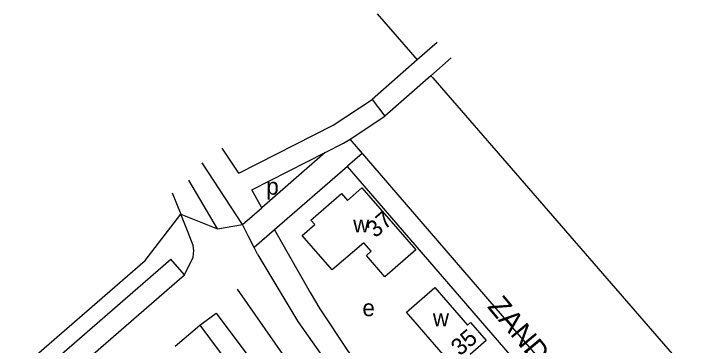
# Model space of a CAD drawing. Extents: x 155854 to 157362, y 383621 to 384685.
# Drawn here: x 156540.2 to 156707.1, y 384605.9 to 384685.4 of the extents above; entities that cross this region are included whole.
import ezdxf

# ---------------------------------------------------------------- set-up
doc = ezdxf.new("R2010")
doc.units = 0
for name, color, linetype in [('BLT_Basislijn', 7, 'Continuous'), ('BLT_Bebouwing', 7, 'Continuous'), ('BLT_Centroide', 7, 'Continuous'), ('BLT_Huisnummer', 7, 'Continuous'), ('BLT_Straatnaam', 7, 'Continuous'), ('BLT_Vlakafsluiter', 7, 'Continuous')]:
    doc.layers.add(name, color=color, linetype=linetype)

msp = doc.modelspace()

# ---------------------------------------------------------------- linework, layer by layer
at = {"layer": 'BLT_Basislijn'}
for p, q in [((156641.66, 384678.54), (156636.87, 384674.33)), ((156636.87, 384674.33), (156626.08, 384664.85)), ((156644.99, 384674.8), (156640.15, 384670.55)), ((156640.15, 384670.55), (156629.12, 384660.87)), ((156738.35, 384519.08), (156620.78, 384655.36)), ((156594.1, 384647.2), (156590.1, 384653.16)), ((156620.17, 384648.93), (156623.7, 384651.98)), ((156595, 384634.87), (156585.33, 384649.64)), ((156588.99, 384633.83), (156582.17, 384645.5)), ((156578.15, 384642.46), (156580.21, 384637.32)), ((156595, 384634.87), (156599.6, 384638.86)), ((156602.64, 384633.55), (156597.78, 384629.33)), ((156597.78, 384629.33), (156596.39, 384632.1)), ((156598.66, 384627.58), (156597.78, 384629.33)), ((156581.09, 384622.79), (156577.82, 384626.56))]:
    msp.add_line(p, q, dxfattribs=at)
for points in [[(156627.31, 384685.36), (156636.87, 384674.33)], [(156640.15, 384670.55), (156640.63, 384670.01)], [(156640.63, 384670.01), (156709.96, 384590.03), (156761.05, 384531.07)], [(156594.1, 384647.2), (156616.73, 384658.67), (156626.08, 384664.85)], [(156620.78, 384655.36), (156629.12, 384660.87)], [(156614.85, 384652.12), (156619.24, 384654.34), (156620.78, 384655.36)], [(156597.21, 384643.17), (156614.85, 384652.12)], [(156614.85, 384652.12), (156599.6, 384638.86)], [(156620.18, 384648.79), (156602.64, 384633.55)], [(156660.68, 384601.84), (156620.18, 384648.79)], [(156599.6, 384638.86), (156597.21, 384643.17)], [(156426.29, 384500), (156571.71, 384626.22), (156580.21, 384637.32)], [(156581.09, 384622.79), (156583.21, 384627.03), (156583.35, 384628.61), (156583.19, 384629.85), (156581.98, 384632.95), (156580.21, 384637.32)], [(156602.64, 384633.55), (156611.21, 384618.58), (156613.55, 384614.63), (156620.14, 384604.65), (156628.52, 384593.18), (156637.24, 384581.48)], [(156598.66, 384627.58), (156608.28, 384611.57), (156621.98, 384592.1), (156632.85, 384577.67)], [(156477.41, 384539.32), (156577.82, 384626.56)], [(156480.66, 384535.59), (156581.09, 384622.79)], [(156593.76, 384619.32), (156609.39, 384596.86), (156624.21, 384576.36)], [(156584.74, 384610.72), (156588.67, 384613.62), (156618, 384574.45), (156619.46, 384572.38), (156619.82, 384570.92), (156619.84, 384569.78), (156619.71, 384568.89), (156619.36, 384567.83), (156618.76, 384566.86), (156617.99, 384566.04), (156614.62, 384570.53)], [(156578.85, 384605.65), (156584.74, 384610.72)], [(156584.74, 384610.72), (156614.62, 384570.53)]]:
    msp.add_lwpolyline(points, dxfattribs=at)
at = {"layer": 'BLT_Bebouwing'}
for p, q in [((156634.31, 384613.86), (156641.11, 384619.73)), ((156641.11, 384619.73), (156648.89, 384610.74)), ((156644.1, 384602.46), (156634.31, 384613.86)), ((156648.89, 384610.74), (156649.63, 384611.37)), ((156649.63, 384611.37), (156653.39, 384607)), ((156653.39, 384607), (156649.52, 384603.65))]:
    msp.add_line(p, q, dxfattribs=at)
msp.add_lwpolyline([(156636.5, 384628.76), (156629.11, 384622.32), (156624.7, 384627.43), (156625.86, 384628.43), (156624.04, 384630.49), (156616.48, 384623.95), (156609.31, 384632.24), (156612.33, 384634.82), (156611.37, 384635.92), (156618.73, 384642.26), (156620.13, 384640.64), (156623.62, 384643.63), (156636.5, 384628.76)], dxfattribs=at)
at = {"layer": 'BLT_Vlakafsluiter'}
for p, q in [((156626.08, 384664.85), (156629.12, 384660.87)), ((156580.21, 384637.32), (156588.99, 384633.83)), ((156588.99, 384633.83), (156595, 384634.87)), ((156596.39, 384632.1), (156595, 384634.87))]:
    msp.add_line(p, q, dxfattribs=at)

# ---------------------------------------------------------------- texts
at = {"layer": 'BLT_Centroide'}
for s, p in [('p', (156600.71, 384642.01)), ('w', (156621.52, 384632.97)), ('e', (156623.74, 384612.87)), ('w', (156640.62, 384610.46))]:
    msp.add_text(s, height=4, dxfattribs=at).set_placement(p)
at = {"layer": 'BLT_Huisnummer'}
for s, p in [('37', (156626.85, 384631.48)), ('35', (156647.12, 384603.17))]:
    msp.add_text(s, height=4, rotation=41.0839, dxfattribs=at).set_placement(p)
at = {"layer": 'BLT_Straatnaam'}
msp.add_text('ZANDOEVER', height=5, rotation=309.7609, dxfattribs=at).set_placement((156653.52, 384615.08))

doc.saveas('drawing.dxf')
